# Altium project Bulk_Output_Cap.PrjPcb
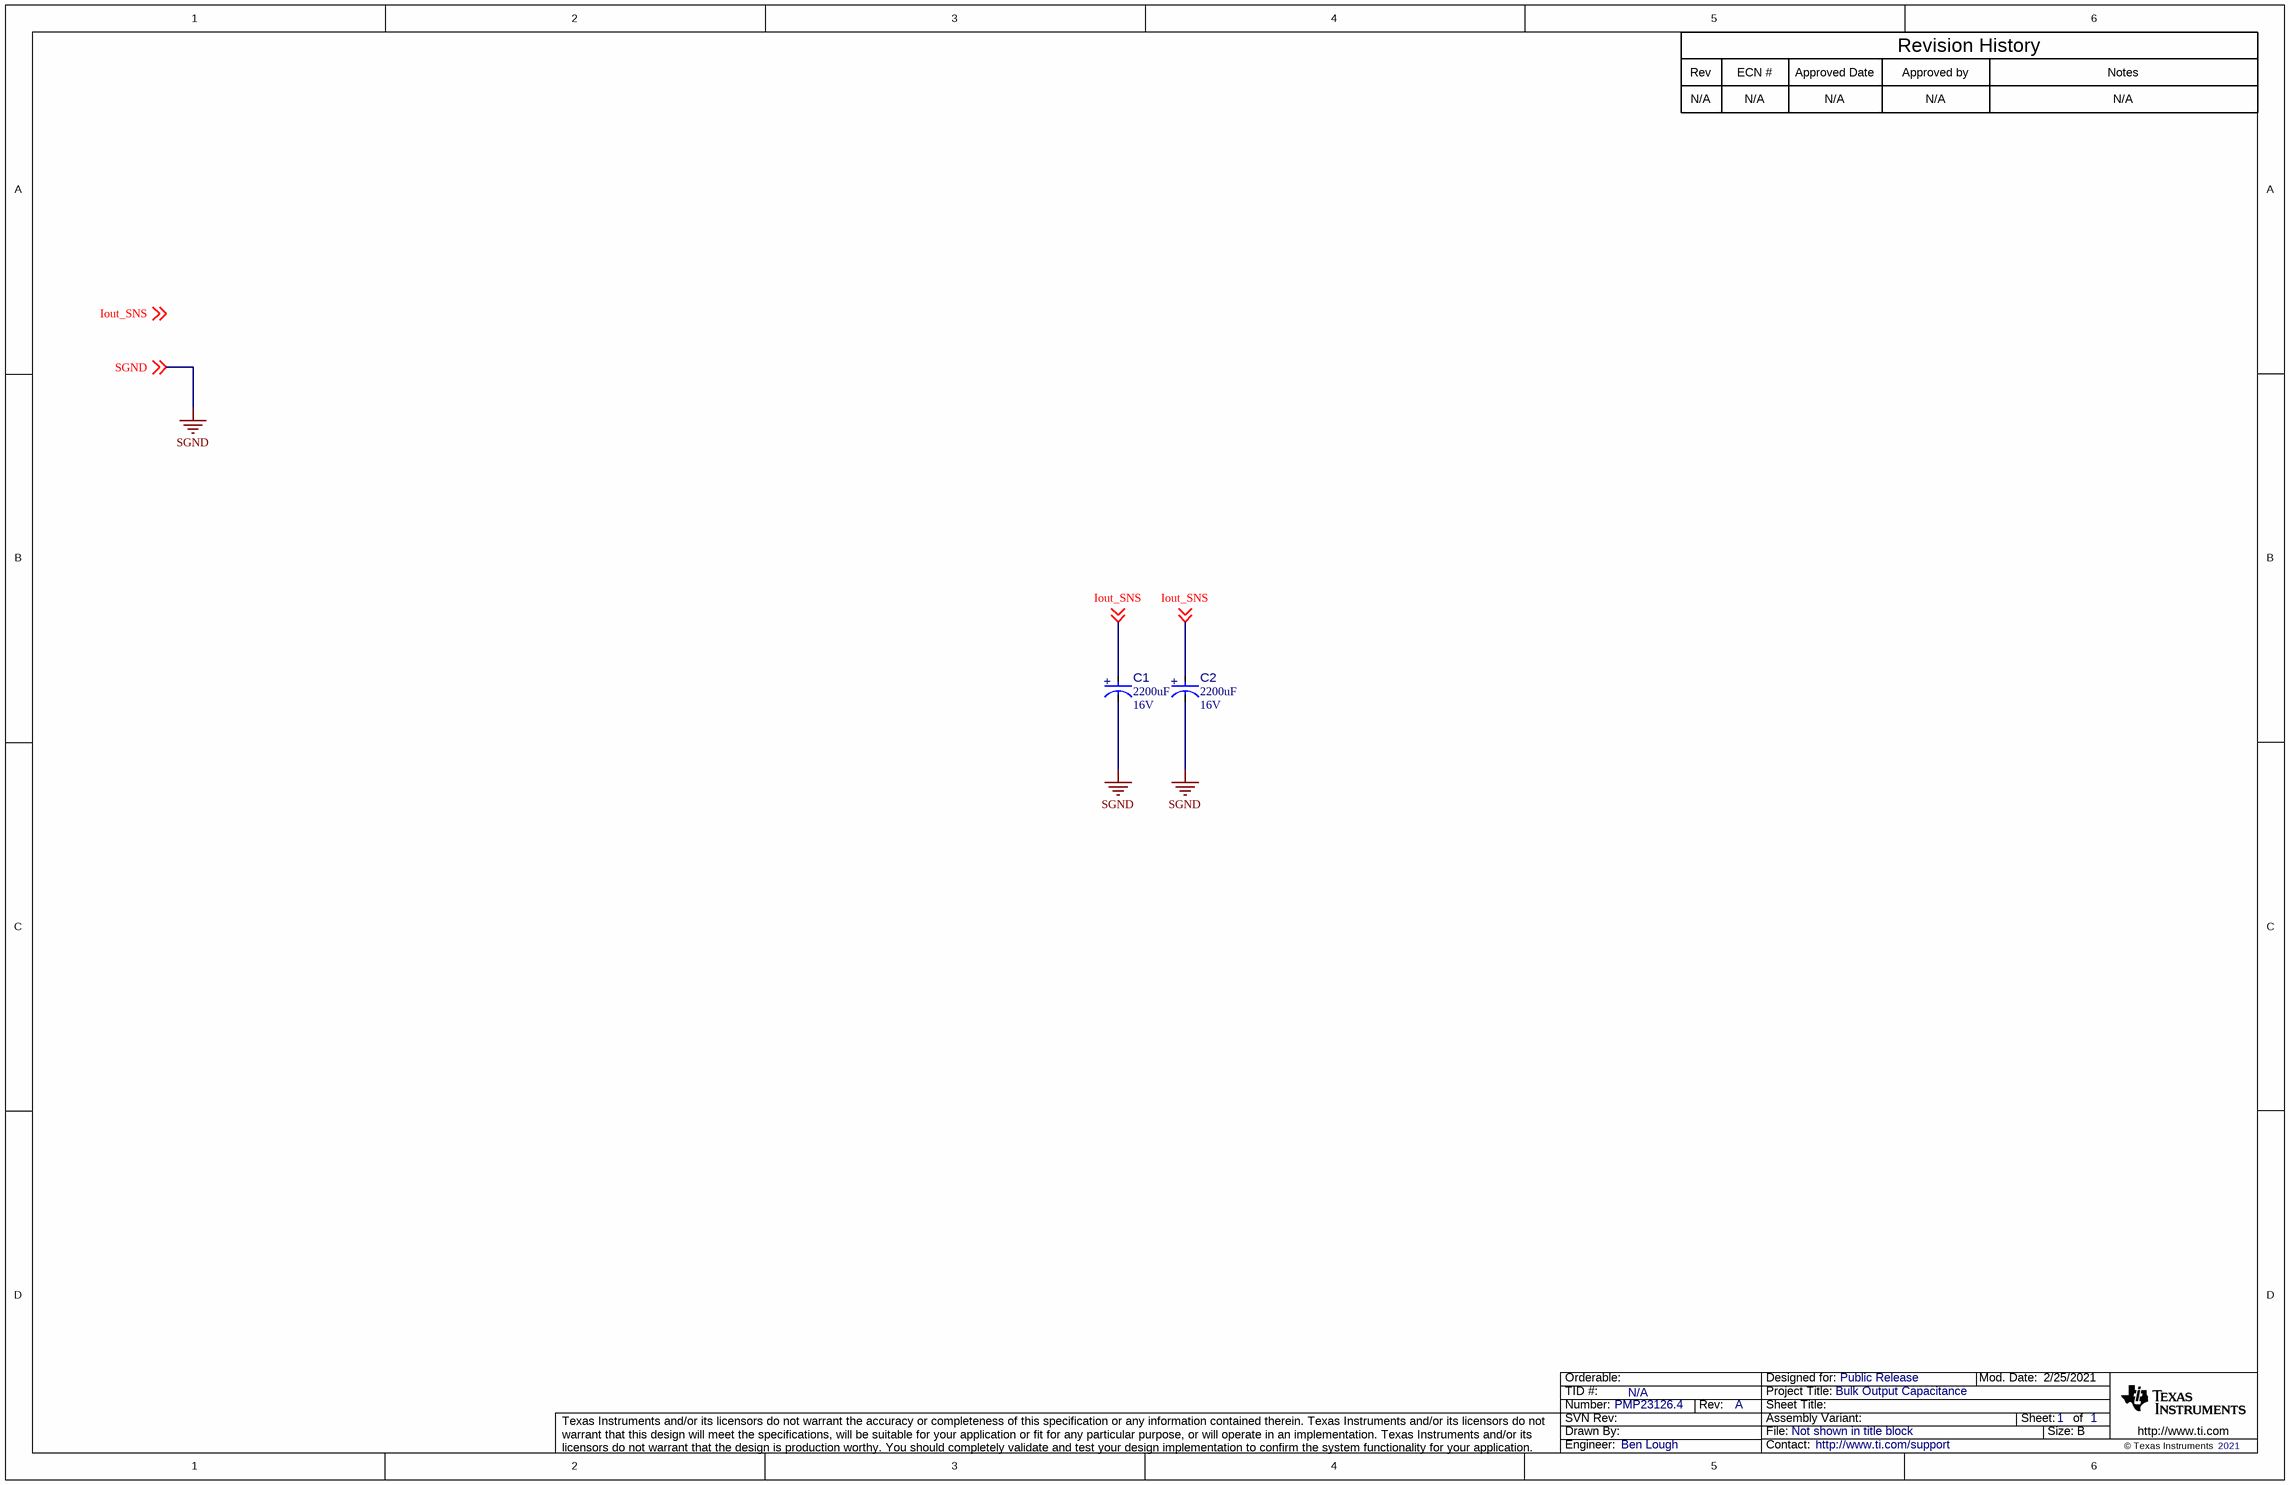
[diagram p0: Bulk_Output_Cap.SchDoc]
CopyrightYear: 2021; PCB_Layout: Ben Lough; PCB_Rev: A; PRJ_Customer: Public Release; PRJ_Engineer: Ben Lough; PRJ_Number: PMP23126.4; PRJ_Title: Bulk Output Capacitance; SCH_Rev: A; TechSupport: http://www.ti.com/support; TID: N/A
1 sheet, 2 parts. Net scope: global (net labels, ports and power ports of the same name join across sheets).
Board file: Bulk_Output_Cap.PcbDoc

## Sheet Bulk_Output_Cap.SchDoc
size 431 x 279 mm; Date: Not shown in title block; ApprovedBy: Not shown in title block; CheckedBy: Not shown in title block; Author: Not shown in title block; CompanyName: Not shown in title block; Engineer: Not shown in title block; Organization: Not shown in title block; Address1: Not shown in title block; Address2: Not shown in title block; Address3: Not shown in title block; Address4: Not shown in title block; DocumentNumber: 1; Revision: Use project parameter SCH_Rev; SheetNumber: 1; SheetTotal: 1; PageSetup: Record=PageOptions¦CenterHorizontal=True¦CenterVertical=True¦PrintScale=1.00¦XCorrection=1.00¦YCorrection=1.00¦PrintKind=0¦BorderSize=5000000¦LeftOffset=0¦BottomOffset=0¦Orientation=2¦PaperLength=1000¦PaperWidth=1000¦Scale=100¦PaperSource=15¦PrintQuality=600¦MediaType=1¦DitherType=10¦PaperKind=Letter¦PrintScaleMode=1

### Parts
C1  ValueDisplayed: 2200uF  VDC_V: 16V  [FP-APSG160ELL222MJ20S_RADIAL-MFG]  (hidden comment: APSG160ELL222MJ20S)
C2  ValueDisplayed: 2200uF  VDC_V: 16V  [FP-APSG160ELL222MJ20S_RADIAL-MFG]  (hidden comment: APSG160ELL222MJ20S)

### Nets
SGND: C1.1(CATHODE) C2.1(CATHODE) ; off-sheet SGND
Iout_SNS: C1.2(ANODE) C2.2(ANODE) ; off-sheet Iout_SNS

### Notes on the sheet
- Rev
- N/A
- ECN #
- Approved Date
- Approved by
- Revision History
- Notes
- Labels drawn without touching a wire or pin: Iout_SNS

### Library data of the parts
C1 C2 = CMP-0094633-1: 2200 µF 16 V Aluminum - Polymer Capacitors Radial, Can 8mOhm 20000 Hrs @ 105°C; Manufacturer: United Chemi-Con; Life: 20000Hours; SizeZ_mm: 21.5mm; Cap_F: 2.2mF; AEC Qualified: No; Value: 2.2mF; Tolerance_%: 20%; Dissipation Factor: 12%; Esr: 8m; IRMS_A: 8.1A; Leakage Current: 7040uA

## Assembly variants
001: not fitted FID1 FID2 FID3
